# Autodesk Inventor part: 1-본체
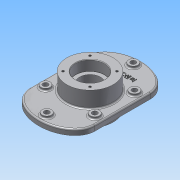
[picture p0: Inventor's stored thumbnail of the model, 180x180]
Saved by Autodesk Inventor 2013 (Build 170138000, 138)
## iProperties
Created: 2015-02
Part Number: 1-본체
Material: 알루미늄 6061
Document SubType Name: Modeling
Designer: Administrator
Mass: 1476.45 g
Surface Area: 942.609 cm^2
Volume: 613.321 cm^3
Density: 2.40731 g/cm^3
Author: Administrator
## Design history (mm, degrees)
sketch "스케치1"
  geometry: L1 (70, -60)-(-70, -60); L2 (-70, -60)-(-70, 60); L3 (-70, 60)-(70, 60); L4 (70, 60)-(70, -60); L5 (70, -60)-(-70, 60); L6 (-70, -60)-(70, 60); 7 further points; 2 other entities
  constraints: 12 end point, 6 midpoint, 2 horizontal, 2 parallel, 2 vertical alignment, 1 perpendicular, 1 vertical, 8 other
  dimensions: "d0" = 140 distance of L1.start L1.end; "d2" = 120 distance of L1.end L2.end; "d3" = 50 distance from line of L3 point (0, 110); "d4" = 50 distance from line of point (0, -110) L1
extrude "돌출1" new body sketch "스케치1" distance "d5" = 12; taper "d6" = 0 deg
node "작업 평면1"
sketch "스케치2"
  geometry: C1 r 50 at (0, 0); 1 further point
  constraints: 1 centre point, 1 coincident
  dimensions: "d8" = 100 diameter of C1
extrude "돌출2" join sketch "스케치2" distance "d10" = 70; taper "d11" = 0 deg
sketch "스케치3"
  geometry: L1 (-70, 60)-(-70, -60) reference; L2 (70, -60)-(70, 60) reference; L3 (-53, 60)-(-53, -60); L4 (53, -60)-(53, 60); C1 r 50 at (0, 0) reference; C2 r 10 at (53, 42.733); C3 r 10 at (53, -42.733); C4 r 10 at (-53, 42.733); C5 r 10 at (-53, -42.733); C6 r 10 at (0, 93); C7 r 10 at (0, -93); 2 further points; 2 other entities
  constraints: 6 centre point, 4 end point, 4 equal radius, 4 point on line, 3 parallel, 2 horizontal alignment, 2 vertical alignment, 10 other
  dimensions: "d12" = 17 distance between parallel lines of L2 L4; "d13" = 20 diameter of C2; "d14" = 20 diameter of C3; "d15" = 85.46667 distance of C3.centre C2.centre; "d16" = 42.73333 vertical distance of C3.centre C1.centre
extrude "돌출3" join sketch "스케치3" distance "d18" = 5; taper "d19" = 0 deg
sketch "스케치4"
  geometry: C1 r 10 at (0, 0) reference; C2 r 10 at (-53, -50.267) reference; C3 r 10 at (53, -50.267) reference; C4 r 10 at (53, -135.733) reference; C5 r 10 at (0, -186) reference; C6 r 10 at (-53, -135.733) reference; 7 further points
  constraints: 6 coincident
hole "구멍1" sketch "스케치4" at (0, 0), (53, -50.267), (-53, -50.267), (-53, -135.733), (0, -186), (53, -135.733) diameter "d20" = 11; stored, may be unused: countersink angle "d24" = 90 deg, drill point angle "d26" = 0 deg; dims "d21" = 6, "d22" = 4, "d23" = 2, "d25" = 8
hole "구멍2" diameter "d29" = 45; stored, may be unused: countersink angle "d33" = 90 deg, drill point angle "d35" = 0 deg; dims "d27" = 10, "d28" = 10, "d30" = 6, "d31" = 62, "d32" = 22, "d34" = 8
hole "구멍3" diameter "d38" = 62; stored, may be unused: countersink angle "d42" = 90 deg, drill point angle "d44" = 0 deg; dims "d39" = 6, "d40" = 62, "d41" = 22, "d43" = 22, "d45" = 10, "d46" = 10
sketch "스케치5"
  geometry: C1 r 50 at (0, 0) reference; 1 further point
  constraints: 1 vertical alignment, 1 other
  dimensions: "d48" = 65 distance of C1.centre point (0, 65)
feature "엠보싱1" sketch "스케치5" dims "d0" = 140, "d2" = 120, "d3" = 50, "d4" = 50, "d49" = 1, "d50" = 0
sketch "스케치6"
  geometry: L1 (28.991, -28.991)-(-28.991, -28.991); L2 (-28.991, -28.991)-(-28.991, 28.991); L3 (-28.991, 28.991)-(28.991, 28.991); L4 (28.991, 28.991)-(28.991, -28.991); L5 (28.991, -28.991)-(-28.991, 28.991); L6 (-28.991, -28.991)-(28.991, 28.991); C1 r 50 at (0, 0) reference; 4 further points
  constraints: 12 end point, 4 coincident, 2 midpoint, 2 parallel, 2 perpendicular, 1 horizontal
  dimensions: "d54" = 82 distance of L1.start L2.end
hole "구멍4" sketch "스케치6" at (-28.991, 28.991), (28.991, 28.991), (28.991, -28.991), (-28.991, -28.991) diameter "d56" = 4.917; stored, may be unused: countersink angle "d60" = 90 deg, drill point angle "d62" = 118 deg; dims "d57" = 10, "d58" = 62, "d59" = 22, "d61" = 13
node "작업 평면2"
fillet "모깎기1" dims "d51" = 3, "d63" = 0.3
chamfer "모따기1" distance "d64" = 1; stored, may be unused: second distance "d65" = 2, angle "d66" = 45 deg
node "솔리드1"
mirror "대칭1"
node "투영된 루프1"
node "투영된 루프2"
node "투영된 루프3"
node "투영된 루프4"
node "투영된 루프5"
other parameters: "d7" = 23
